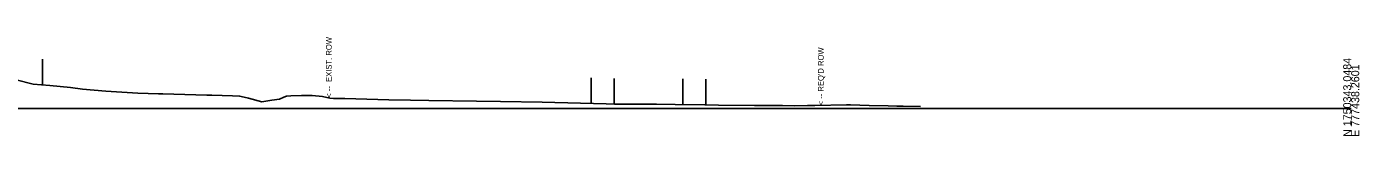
# Model space of a CAD drawing. Extents: x 776426 to 854588, y 1736205 to 1756790.
# Drawn here: x 805207.3 to 805673.6, y 1750205.1 to 1750239.8 of the extents above; entities that cross this region are included whole.
import ezdxf

# ---------------------------------------------------------------- set-up
doc = ezdxf.new("R2010")
doc.units = 0
for name, color, linetype in [('63', 7, 'Continuous'), ('DTM CONTOURS_MAJOR_TX', 7, 'Continuous'), ('DTM_X_FLOW_ARROWS', 7, 'Continuous'), ('TRANS_EOP_PAVED', 7, 'Continuous'), ('TRANS_UNPAVED_SHOULDERS', 7, 'Continuous'), ('XS_P_ROW', 7, 'Continuous'), ('XS_X_ROW', 7, 'Continuous')]:
    doc.layers.add(name, color=color, linetype=linetype)

msp = doc.modelspace()

# ---------------------------------------------------------------- linework, layer by layer
at = {"layer": '63'}
msp.add_line((805212.81, 1750231.98), (805212.81, 1750222.98), dxfattribs=at)
msp.add_line((805212.81, 1750231.98), (805212.81, 1750222.98), dxfattribs=at)
at = {"layer": 'DTM CONTOURS_MAJOR_TX'}
msp.add_line((805170.79, 1750214.76), (805670.79, 1750214.76), dxfattribs=at)
at = {"layer": 'DTM_X_FLOW_ARROWS'}
msp.add_lwpolyline([(805203.64, 1750224.73), (805209.57, 1750223.29), (805215.42, 1750222.72), (805222.69, 1750222.01), (805226.9, 1750221.45), (805235.02, 1750220.82), (805246.18, 1750220.07), (805253.44, 1750219.87), (805254.94, 1750219.83), (805270.36, 1750219.39), (805272.05, 1750219.33), (805279.36, 1750219.13), (805281.82, 1750219.04), (805283.45, 1750218.66), (805284.88, 1750218.32), (805289.57, 1750217.04), (805293.05, 1750217.58), (805295.79, 1750217.99), (805297.28, 1750218.67), (805298.26, 1750219.06), (805299.7, 1750219.18), (805303.45, 1750219.22), (805306.3, 1750219.31), (805307.2, 1750219.22), (805310.86, 1750218.87), (805313.43, 1750218.38), (805314.73, 1750218.26), (805316.85, 1750218.24), (805318.6, 1750218.27), (805334.05, 1750217.74), (805341.6, 1750217.63), (805348.04, 1750217.54), (805364.67, 1750217.32), (805373.08, 1750217.2), (805387.74, 1750216.98), (805410.1, 1750216.33), (805413.04, 1750216.26), (805413.43, 1750216.22), (805415.24, 1750216.23), (805427.71, 1750216.21), (805434.25, 1750216.1), (805444.63, 1750215.97), (805449.4, 1750215.91), (805462.02, 1750215.76), (805465.55, 1750215.76), (805467.65, 1750215.75), (805471.78, 1750215.72), (805475.9, 1750215.7), (805480.53, 1750215.72), (805483.05, 1750215.74), (805494.18, 1750216), (805494.91, 1750216.01), (805495.63, 1750215.99), (805502.13, 1750215.78), (805508.8, 1750215.69), (805511.76, 1750215.57), (805514.06, 1750215.57), (805520.1, 1750215.37)], dxfattribs=at)
at = {"layer": 'TRANS_EOP_PAVED'}
for p, q in [((805412.86, 1750225.27), (805412.86, 1750216.27)), ((805412.86, 1750225.27), (805412.86, 1750216.27)), ((805436.97, 1750225.07), (805436.97, 1750216.07)), ((805436.97, 1750225.07), (805436.97, 1750216.07))]:
    msp.add_line(p, q, dxfattribs=at)
at = {"layer": 'TRANS_UNPAVED_SHOULDERS'}
for p, q in [((805404.82, 1750225.48), (805404.82, 1750216.48)), ((805404.82, 1750225.48), (805404.82, 1750216.48)), ((805445.01, 1750224.96), (805445.01, 1750215.96)), ((805445.01, 1750224.96), (805445.01, 1750215.96))]:
    msp.add_line(p, q, dxfattribs=at)

# ---------------------------------------------------------------- texts
at = {"layer": 'DTM CONTOURS_MAJOR_TX'}
for s, p in [('N 1750343.0484', (805670.79, 1750204.76)), ('E 777438.2601', (805673.59, 1750204.76))]:
    msp.add_text(s, height=2.8, rotation=90, dxfattribs=at).set_placement(p)
at = {"layer": 'XS_P_ROW'}
msp.add_text("< -- REQ'D ROW", height=2, rotation=90, dxfattribs=at).set_placement((805486.19, 1750215.79))
at = {"layer": 'XS_X_ROW'}
msp.add_text('< --  EXIST. ROW', height=2, rotation=90, dxfattribs=at).set_placement((805314.06, 1750218.45))

doc.saveas('drawing.dxf')
